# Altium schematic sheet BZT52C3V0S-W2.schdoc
size 127 x 101 mm
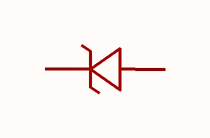
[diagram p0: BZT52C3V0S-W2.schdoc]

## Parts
D?  bzt52c3v0s_c523830  [SOD-323_L1.6-W1.3-LS2.7-RD]  (value not drawn)

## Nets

Not connected (* = marked no-connect by the designer): D? 1(K) 2(A)

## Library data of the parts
D? = bzt52c3v0s_c523830: 二极管配置:1个独立式;稳压值(标称值):3V;稳压值(范围):2.8V~3.2V;耗散功率(Pd):200mW;; Manufacturer: MDD(辰达半导体); Symbol: BZT52C3V0S-W2; AddInBom: yes; ModelId: 39bca86493a8419684ee2090e9340edf; ModelTransform: 104.3305,51.181,0,0,0,0,0,0,0; Diode Configuration: 1个独立式; Zener Voltage(Nom): 3V; Reverse Leakage Current (Ir): 50uA@1V; Pd - Power Dissipation: 200mW; Impedance(Zzt): 120Ω; Tolerance: ±5%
